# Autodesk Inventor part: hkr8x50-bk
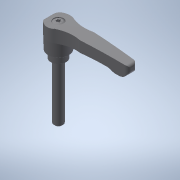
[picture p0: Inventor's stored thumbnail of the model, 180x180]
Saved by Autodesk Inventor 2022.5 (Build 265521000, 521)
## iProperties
Created: 2017-09
Part Number: hkr8x50-bk
Material: 一般
Document SubType Name: Modeling
Designer: imaocorp
Density: 1 g/cm^3
Appearance: 既定
Author: imaocorp
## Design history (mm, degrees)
node "hkr8x50-bk.x_t1"
node "hkr8x50-bk"
node "Base1"
